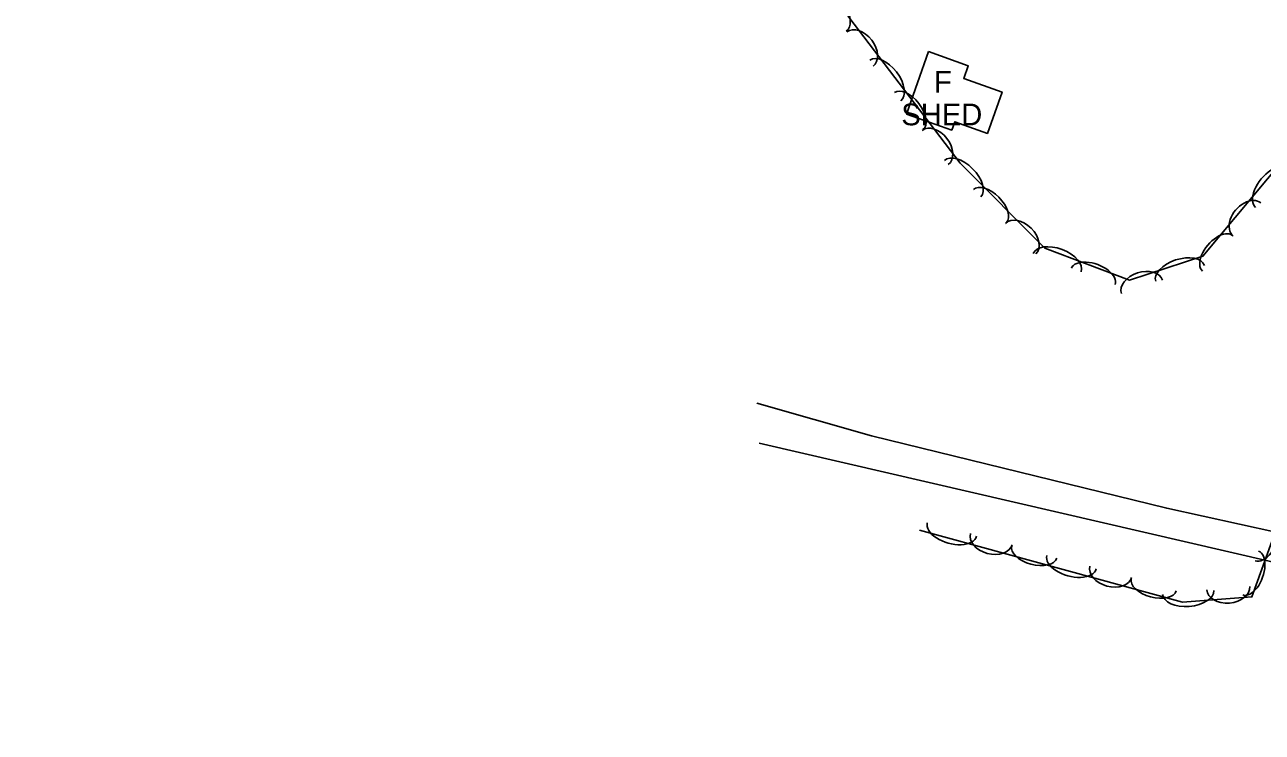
# Model space of a CAD drawing. Extents: x 1441650 to 1491889, y 345904 to 358319.
# Drawn here: x 1445002 to 1445285.8, y 354563.6 to 354726 of the extents above; entities that cross this region are included whole.
import ezdxf

# ---------------------------------------------------------------- set-up
doc = ezdxf.new("R2010")
doc.units = 0
for name, color, linetype in [('S_BUILDING', 7, 'Continuous'), ('S_BUILDING_ANNOT', 7, 'Continuous'), ('S_STREAM', 7, 'Continuous'), ('S_TREE', 7, 'Continuous')]:
    doc.layers.add(name, color=color, linetype=linetype)

msp = doc.modelspace()

# ---------------------------------------------------------------- linework, layer by layer
at = {"layer": 'S_BUILDING'}
msp.add_lwpolyline([(1445209.3, 354719.78), (1445204.23, 354705.45), (1445214.6, 354701.78), (1445215.28, 354703.69), (1445222.78, 354701.03), (1445226.13, 354710.5), (1445217.35, 354713.61), (1445218.4, 354716.56)], close=True, dxfattribs=at)
at = {"layer": 'S_STREAM'}
msp.add_lwpolyline([(1445170.45, 354629.91), (1445297.62, 354600.44), (1445335.35, 354590.73), (1445382.3, 354576.96), (1445442.67, 354563.55), (1445426.74, 354572.49), (1445368.62, 354588.85), (1445326.19, 354600.02), (1445288.92, 354609.46), (1445263.91, 354614.98), (1445196.19, 354631.56), (1445169.91, 354639.11)], dxfattribs=at)
at = {"layer": 'S_TREE'}
for points in [[(1445062.66, 354737.7), (1445036.25, 354743.75), (1445018.34, 354758.77), (1445002, 354780.57), (1445008.72, 354803.48), (1445034.19, 354809.69), (1445078.19, 354795.67), (1445109.88, 354793.21), (1445132.32, 354802.76), (1445141.03, 354825.37), (1445149.69, 354845.03), (1445168.23, 354849.09), (1445178.41, 354829.92), (1445171.6, 354792.55), (1445175.47, 354753.75), (1445190.97, 354727.66), (1445216.54, 354694.19), (1445235.93, 354674.69), (1445255.34, 354667.34), (1445272.22, 354672.85), (1445290.88, 354695.22)], [(1445305.4, 354655.37), (1445283.45, 354594.64), (1445267.53, 354593.43), (1445207.2, 354609.91)]]:
    msp.add_lwpolyline(points, dxfattribs=at)
for centre, major_axis, ratio, start_param, end_param in [((1445187.64, 354729.11), (-2.73, 4.6), 0.540684, 3.141593, 6.283185), ((1445193.54, 354720.37), (-3.01, 3.94), 0.685303, 3.141593, 6.283185), ((1445199.37, 354713.17), (-3.56, 4.66), 0.550073, 3.141593, 6.283185), ((1445204.75, 354706.13), (-3.25, 4.25), 0.540693, 3.141593, 6.283185), ((1445210.8, 354697.78), (-3.01, 3.94), 0.685303, 3.141593, 6.283185), ((1445217.1, 354690.63), (-4.14, 4.16), 0.550079, 3.141593, 6.283185), ((1445288.05, 354688.51), (-3.75, -4.5), 0.550411, 3.140771, 6.282364), ((1445223.35, 354684.34), (-3.77, 3.79), 0.540698, 3.141593, 6.283185), ((1445282.32, 354681.24), (-3.17, -3.81), 0.685723, 3.140246, 6.281839), ((1445230.43, 354676.85), (-3.49, 3.51), 0.68531, 3.141593, 6.283185), ((1445275.53, 354673.5), (-3.42, -4.1), 0.541025, 3.140797, 6.28239), ((1445238.78, 354671.34), (-5.49, 2.08), 0.55006, 3.141583, 6.283175), ((1445247.07, 354668.2), (-5, 1.89), 0.54068, 3.141583, 6.283176), ((1445266.95, 354668.89), (-5.58, -1.82), 0.549958, 3.141593, 6.283185), ((1445258.23, 354665.77), (-4.71, -1.54), 0.685159, 3.141593, 6.283185), ((1445286.19, 354608.44), (2, 5.52), 0.550035, 3.141933, 6.283526), ((1445214.65, 354610.08), (5.66, -1.55), 0.550058, 3.141642, 6.283235), ((1445223.65, 354607.89), (4.78, -1.31), 0.685283, 3.141674, 6.283266), ((1445233.51, 354604.92), (5.16, -1.41), 0.540678, 3.141641, 6.283233), ((1445242.07, 354602.58), (5.66, -1.55), 0.550058, 3.141642, 6.283235), ((1445283.17, 354600.1), (1.82, 5.03), 0.540656, 3.141922, 6.283515), ((1445251.07, 354600.4), (4.78, -1.31), 0.685283, 3.141674, 6.283266), ((1445260.94, 354597.43), (5.16, -1.41), 0.540678, 3.141641, 6.283233), ((1445278.03, 354596.61), (4.94, 0.37), 0.685206, 3.141593, 6.283185), ((1445268.82, 354595.65), (5.85, 0.44), 0.549996, 3.141593, 6.283185)]:
    msp.add_ellipse(centre, major_axis=major_axis, ratio=ratio, start_param=start_param, end_param=end_param, dxfattribs=at)

# ---------------------------------------------------------------- texts
at = {"layer": 'S_BUILDING_ANNOT'}
for s, p in [('F', (1445210.53, 354710.37)), ('SHED', (1445203.03, 354702.87))]:
    msp.add_text(s, height=5, dxfattribs=at).set_placement(p)

doc.saveas('drawing.dxf')
